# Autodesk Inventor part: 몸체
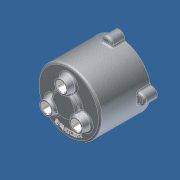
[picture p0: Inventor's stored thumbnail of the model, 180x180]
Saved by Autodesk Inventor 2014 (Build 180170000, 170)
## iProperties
Created: 2012-05
Part Number: 몸체
Document SubType Name: 모델링
Designer: SeoGD™
Material: 일반
Appearance: 기본값
변환 표준: STEP AP214IS
파일 이름: C:\Users\SeoGD\Desktop\?쒗뿕\紐몄껜.stp
전처리기: Build: 253, Release: 2010 SP1 - Date: Wed 07/29/2009
전송 단위: 밀리미터
불확실성: 0.01
Author: SeoGD™
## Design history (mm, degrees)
sketch "스케치2"
  geometry: C1 r 50 at (0, 0); 1 further point
  constraints: 1 centre point, 1 coincident
  dimensions: "d9" = 100 diameter of C1
extrude "돌출2" new body sketch "스케치2" distance "d10" = 80; taper "d11" = 0 deg
feature "쉘1" dims "d12" = 5
sketch "스케치3" dims "d13" = 55
  geometry: C1 r 7.5 at (0, 27.5); C2 r 12.5 at (0, 27.5); 2 further points
  constraints: 2 centre point, 2 coincident, 2 vertical alignment, 2 other
  dimensions: "d14" = 15 diameter of C1; "d15" = 25 diameter of C2
extrude "돌출3" join sketch "스케치3" distance "d16" = 12; taper "d17" = -10 deg
hole "구멍2" diameter "d20" = 15; stored, may be unused: countersink angle "d24" = 90 deg, drill point angle "d26" = 118 deg; dims "d18" = 10, "d19" = 10, "d21" = 6, "d22" = 4, "d23" = 2, "d25" = 15
chamfer "모따기1" distance "d27" = 1; stored, may be unused: second distance "d28" = 2, angle "d29" = 45 deg
sketch "스케치4"
  geometry: L1 (0, 0)-(0, 88); L2 (0, 70)-(13.16, 70); L3 (-45, 75)-(45, 75) reference; L4 (-50, 80)-(50, 80) reference; L5 (13.16, 70)-(14.5, 75); L6 (20, 80)-(20, 88); L7 (20, 88)-(0, 88); L8 (20, 80)-(14.5, 75)
  constraints: 12 end point, 3 point on line, 2 perpendicular, 1 vertical
  dimensions: "d34" = 40 diameter of L6 L1; "d35" = 105 deg angle of L5 L3; "d36" = 5 distance between parallel lines of L2 L3; "d37" = 8 distance between parallel lines of L7 L4; "d51" = 29 diameter of L5.end L1
revolve "회전1" sketch "스케치4" stored, may be unused: angle "d38" = 90 deg
hole "구멍3" diameter "d41" = 15; stored, may be unused: countersink angle "d45" = 90 deg, drill point angle "d47" = 0 deg; dims "d39" = 10, "d40" = 10, "d42" = 6, "d43" = 22, "d44" = 13, "d46" = 15
chamfer "모따기2" distance "d48" = 1; stored, may be unused: second distance "d49" = 2, angle "d50" = 45 deg
fillet "모깎기1" dims "d52" = 3
fillet "모깎기2" dims "d53" = 3, "d72" = 0.2
sketch "스케치5"
  geometry: A1 r 50 centre (0, 0) between (50, 0) and (-8.074, 49.344) reference; A2 r 8.5 centre (0, 52) between (8.074, 49.344) and (-8.074, 49.344); 1 further point
  constraints: 5 point on circle, 1 centre point, 1 horizontal alignment
  dimensions: "d54" = 90 deg dimension on point (0, 0) A2.centre A1.start; "d55" = 52 distance of A2.centre point (0, 0); "d56" = 17 diameter of A2
extrude "돌출4" join sketch "스케치5" distance "d57" = 20; taper "d58" = 0 deg
fillet "모깎기3" dims "d59" = 3
hole "구멍4" diameter "d62" = 4.134; stored, may be unused: countersink angle "d66" = 90 deg, drill point angle "d68" = 118 deg; dims "d60" = 10, "d61" = 10, "d63" = 12, "d64" = 22, "d65" = 13, "d67" = 15
sketch "스케치6"
  geometry: C1 r 47 at (0, 0) reference; C2 r 42.5 at (0, 0); 1 further point
  constraints: 1 centre point, 1 coincident, 1 other
  dimensions: "d73" = 85 diameter of C2
feature "엠보싱1" sketch "스케치6" dims "d74" = 1, "d75" = 0
node "솔리드1"
node "솔리드 본체"
node "곡면 본체"
pattern_circular "원형 패턴1" dims "d31" = 360 deg
pattern_circular "원형 패턴2" dims "d70" = 360 deg
node "솔리드2"
